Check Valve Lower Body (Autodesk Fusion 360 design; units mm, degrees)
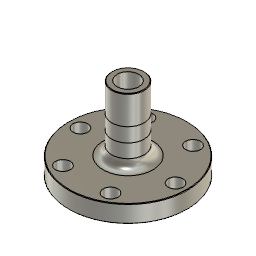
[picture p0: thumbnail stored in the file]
sketch "Sketch1" plane through (0, 0, 0) normal (0, 1, 0) x axis (1, 0, 0)
  line L1 (17.399, -5.08) -> (17.399, 0)
  line L2 (3.175, -5.08) -> (3.175, -1.778)
  line L3 (17.399, -5.08) -> (4.7625, -5.08)
  line L4 (0, -14.1049) -> (0, 0)
  line L5 (6.985, -1.778) -> (6.985, 0)
  line L6 (6.3881, -1.778) -> (6.985, -1.778)
  line L7 (3.8227, -2.8448) -> (6.3881, -2.8448)
  line L8 (3.8227, -2.8448) -> (3.8227, -1.778)
  line L9 (6.3881, -1.778) -> (6.3881, -2.8448)
  line L10 (3.175, -1.778) -> (3.8227, -1.778)
  line L11 (4.7625, -24.13) -> (4.7625, -5.08)
  line L12 (3.175, -24.13) -> (4.7625, -24.13)
  line L13 (3.175, -5.08) -> (3.175, -24.13)
  line L14 (7.7978, -1.0668) -> (7.7978, 0)
  line L15 (10.3632, -1.0668) -> (7.7978, -1.0668)
  line L16 (10.3632, 0) -> (10.3632, -1.0668)
  line L17 (10.3632, 0) -> (17.399, 0)
  line L18 (6.985, 0) -> (7.7978, 0)
  point P1 (0, 0)
  point P6 (0, 0)
  point P2 (17.399, 0)
  point P3 (17.399, -5.08)
  point P8 (6.985, 0)
  point P9 (6.985, -1.778)
  point P11 (3.8227, -1.778)
  point P12 (3.8227, -2.8448)
  point P13 (6.3881, -2.8448)
  coincident P1 P6
  horizontal L7
  vertical L9
  horizontal L6
  collinear L6 L10
  vertical L8
  horizontal L3
  vertical L5
  coincident P1 L17
  horizontal L17
  vertical L11
  horizontal L12
  vertical L13
  vertical L14
  horizontal L15
  vertical L16
  collinear L17 L18
  dimension "d3" distance P2 P3 = 5.08
  dimension "d64" distance P8 P9 = 1.778
  dimension "d90" distance P11 P12 = 1.0668
  dimension "d94" distance P12 P13 = 2.5654
  dimension "d111" = 7.6454
  dimension "d112" = 6.35
  dimension "d113" = 34.798
  dimension "d114" = 9.525
  dimension "d115" distance L3 L12 = 19.05
  dimension "d116" = 13.97
  dimension "d117" = 20.7264
  dimension "d118" distance L15 L18 = 1.0668
  dimension "d119" distance L14 L16 = 2.5654
revolve "Revolve1" sketch "Sketch1" AlongAngle 360
sketch "Sketch14" plane through (0, 0, 0) normal (0, 0, 1) x axis (1, 0, 0)
  line L1 (0, 0) -> (13.97, 0)
  circle C1 centre (13.97, 0) radius 2.3767
  point P2 (13.97, 0)
  point P3 (13.97, 0)
  point P1 (0, 0)
  point P4 (0, 0)
  coincident P2 P3
  coincident P1 P4
  horizontal L1
  dimension "d120" distance P1 P2 = 13.97
hole "Hole4" HoleDiameter 4.3053 TipAngle 118
circular_pattern "C-Pattern2" TotalAngle 360
chamfer "Chamfer1" distance 0.1524
chamfer "Chamfer2" distance 0.1524
fillet "Fillet1" radius 2.54
work_plane "WorkPlane1" AlongDistance -8.382
work_plane "WorkPlane2" AlongDistance -4.1402
split_face "SplitFace1"
chamfer "Chamfer3" distance 0.127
